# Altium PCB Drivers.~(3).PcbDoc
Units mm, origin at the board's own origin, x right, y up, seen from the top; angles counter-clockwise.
Board outline 55.43 x 48 mm, 2 copper layers (F.Cu, B.Cu); 24 components, 42 nets, 131 pads, 0 vias.
Unrouted connection lines stored in the file: 89.
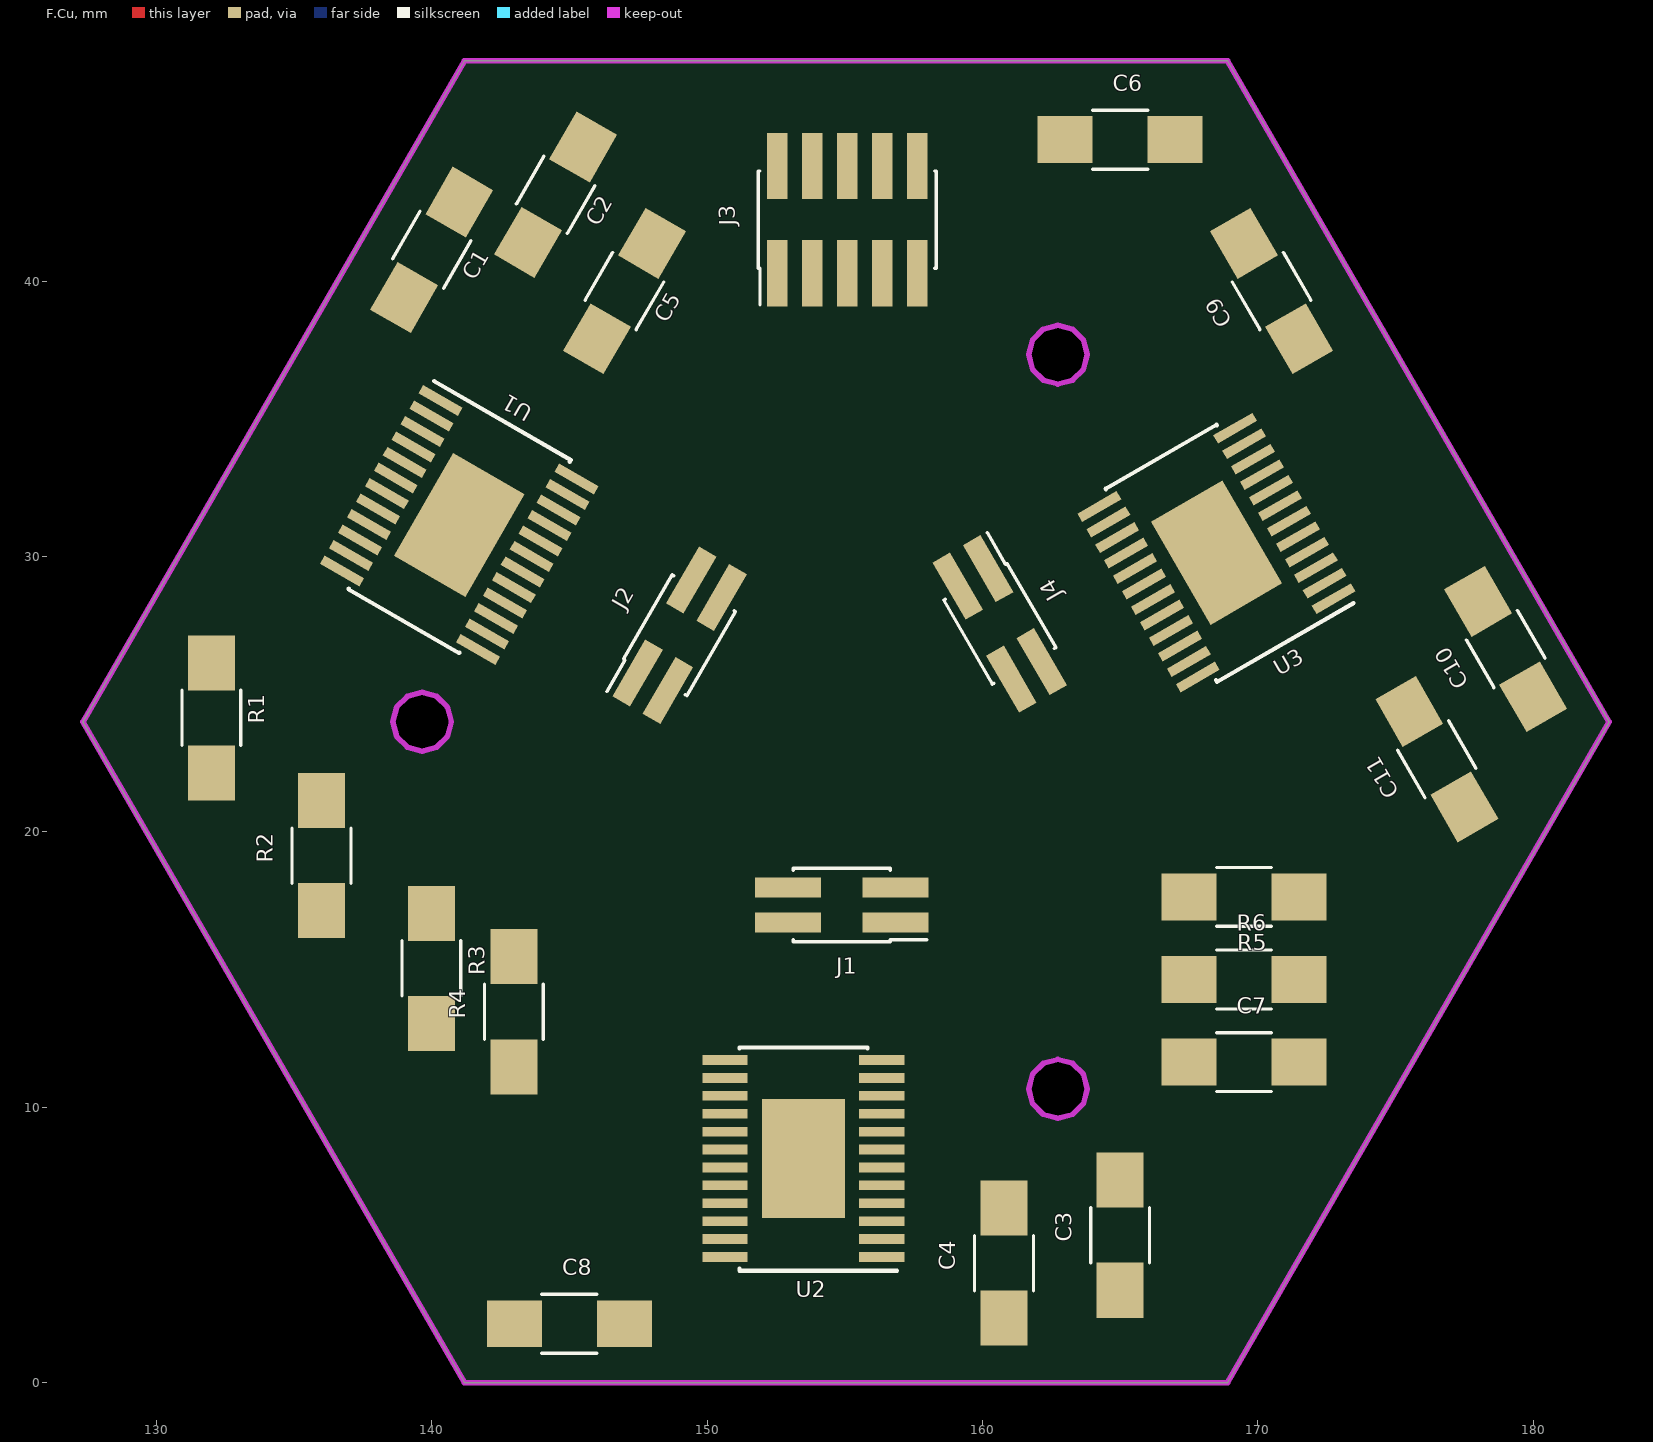
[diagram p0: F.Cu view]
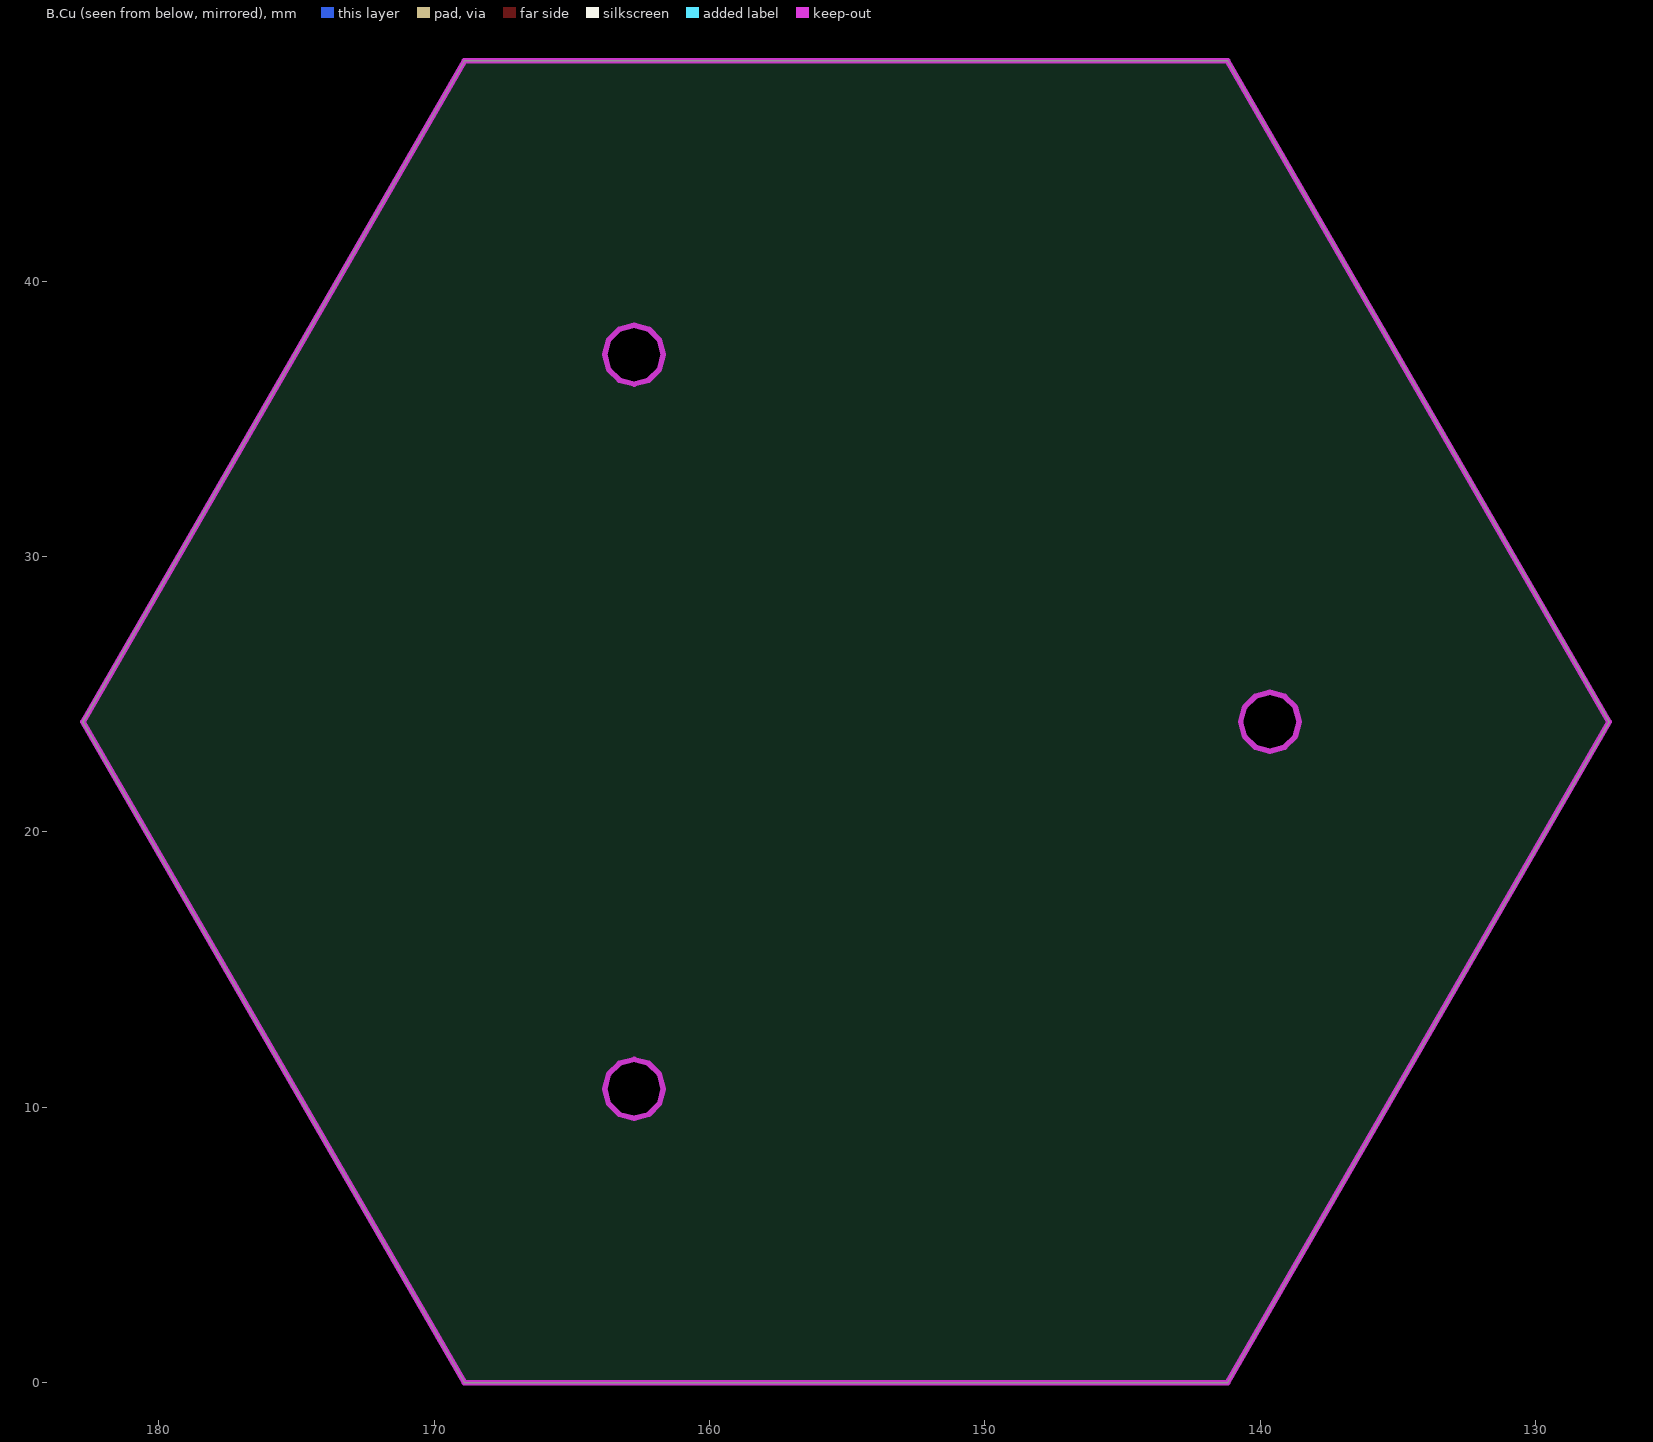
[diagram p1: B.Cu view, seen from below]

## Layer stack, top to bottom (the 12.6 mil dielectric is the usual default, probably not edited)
F.Mask: solder mask 0.0102, Solder Resist, Dk 3.5
F.Cu: signal copper 0.0356
Dielectric 1: dielectric 0.32, FR-4, Dk 4.8
B.Cu: signal copper 0.0356
B.Mask: solder mask 0.0102, Solder Resist, Dk 3.5

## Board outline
168.902,0 182.758,24 168.902,48 141.189,48 127.333,24 141.189,0 168.902,0
cut-out: 139.649,25.067 139.116,24.924 138.726,24.534 138.583,24 138.726,23.467 139.116,23.076 139.649,22.934 140.183,23.076 140.573,23.467 140.716,24 140.573,24.534 140.183,24.924 139.649,25.067
cut-out: 162.743,9.597 163.278,9.74 163.668,10.132 163.81,10.667 163.668,11.202 163.278,11.593 162.743,11.737 162.209,11.593 161.818,11.202 161.677,10.667 161.818,10.132 162.209,9.74 162.743,9.597
cut-out: 163.278,38.26 162.743,38.404 162.209,38.26 161.818,37.868 161.677,37.334 161.818,36.799 162.209,36.407 162.743,36.264 163.278,36.407 163.668,36.799 163.81,37.334 163.668,37.868 163.278,38.26

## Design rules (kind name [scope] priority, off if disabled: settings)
Clearance "Clearence 0.4_NetClass" [InNetClass('Back')] p1: gap=0.4 ignorepadtopadclearanceinfootprint=FALSE
Clearance "Clearence 0.28_NetClass" [InNetClass('Default')] p2: gap=0.28 ignorepadtopadclearanceinfootprint=FALSE
HoleSize "Hole Size (Default)" [All] p1: absolutevalues=TRUE maxlimit=10 minlimit=0.3 maxpercent=80.000 minpercent=20.000
MinimumSolderMaskSliver [All] p1: minsoldermaskwidth=0
PolygonConnect [All] p1: connectstyle=Direct reliefconductorwidth=0.254 reliefentries=4 polygonreliefangle="90 Angle" airgapwidth=0.254
RoutingVias [All] p1: holewidth=0.711 width=1.27 viastyle="Through Hole" minholewidth=0.711 minwidth=1.27 maxholewidth=0.711 maxwidth=1.27
SilkToSilkClearance [All] p1: silktosilkclearance=0
SilkToSolderMaskClearance [IsPad] p1: minsilkscreentomaskgap=0 clearancetoexposedcopper=TRUE
SolderMaskExpansion [All] p1: expansion=0.102 istentingtop=FALSE
Width [All] p1: maxlimit=0.254 minlimit=0.254 preferedwidth=0.254
26 further rules are at their usual default settings.

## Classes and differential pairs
net class Default: 1_1A 1_1B 1_2A 1_2B 1_DIR 1_STEP 2_1A 2_1B 2_2A 2_2B 2_DIR 2_STEP 3.3V 3_1A 3_1B 3_2A 3_2B 3_DIR 3_STEP 9V 12V GND MS1 Net-(C1-Pad1) Net-(C2-Pad1) Net-(C2-Pad2) Net-(C3-Pad1) Net-(C4-Pad1) Net-(C4-Pad2) Net-(C5-Pad2) Net-(C8-Pad2) Net-(C9-Pad1) Net-(C10-Pad1) Net-(C10-Pad2) Net-(C11-Pad2) Net-(R1-Pad1) Net-(R2-Pad2) Net-(R3-Pad1) Net-(R4-Pad2) Net-(R5-Pad1) Net-(R6-Pad2) RESET

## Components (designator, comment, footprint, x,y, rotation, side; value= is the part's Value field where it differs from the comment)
C1 "0.22uF" C_1206 140,41.14 r240 top
C2 "0.1uF" C_1206 144.5,43.14 r240 top
C3 "0.22uF" C_1206 165,5.357 r90 top
C4 "0.1uF" C_1206 160.782,4.341 r90 top
C5 "0.1uF" C_1206 147,39.64 r240 top
C6 "0.22uF" C_1206 165,45.14 r0 top
C7 "100uF" C_1206 169.5,11.64 r0 top
C8 "0.1uF" C_1206 145,2.14 r0 top
C9 "0.22uF" C_1206 170.5,39.64 r120 top
C10 "0.1uF" C_1206 179,26.64 r120 top
C11 "0.1uF" C_1206 176.5,22.64 r120 top
J1 "Conn_02x02" PinHeader_2x02_P1.27mm_Vertical_SMD 154.889,17.345 r180 top
J2 "Conn_02x02" PinHeader_2x02_P1.27mm_Vertical_SMD 149,27.14 r60 top
J3 "Conn_PinHeader_2x05_P1.27mm_Vertical_SMD" PinHeader_2x05_P1.27mm_Vertical_SMD 155.092,42.237 r90 top
J4 "Conn_02x02" PinHeader_2x02_P1.27mm_Vertical_SMD 160.63,27.556 r300 top
R1 "3.4" R_1206 132,24.14 r270 top
R2 "3.4" R_1206 136,19.14 r90 top
R3 "3.4" R_1206 139.989,15.043 r270 top
R4 "3.4" R_1206 142.986,13.469 r90 top
R5 "3.4" R_1206 169.5,17.64 r180 top
R6 "3.4" R_1206 169.5,14.64 r0 top
U1 "MotorDriver_BipolarStepper_A4982" 24-TSSOP-EP 141,31.14 r330 top
U2 "MotorDriver_BipolarStepper_A4982" 24-TSSOP-EP 153.5,8.14 r180 top
U3 "MotorDriver_BipolarStepper_A4982" 24-TSSOP-EP 168.5,30.14 r210 top

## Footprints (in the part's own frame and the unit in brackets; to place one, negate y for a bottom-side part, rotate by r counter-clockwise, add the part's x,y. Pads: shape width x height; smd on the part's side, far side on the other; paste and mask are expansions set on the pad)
24-TSSOP-EP [mm]
  rect 1.65x0.35 smd mask+0: 1(-2.85,3.575) 2(-2.85,2.925) 3(-2.85,2.275) 4(-2.85,1.625) 5(-2.85,0.975) 6(-2.85,0.325) 7(-2.85,-0.325) 8(-2.85,-0.975) 9(-2.85,-1.625) 10(-2.85,-2.275) 11(-2.85,-2.925) 12(-2.85,-3.575) 13(2.85,-3.575) 14(2.85,-2.925) 15(2.85,-2.275) 16(2.85,-1.625) 17(2.85,-0.975) 18(2.85,-0.325) 19(2.85,0.325) 20(2.85,0.975) 21(2.85,1.625) 22(2.85,2.275) 23(2.85,2.925) 24(2.85,3.575)
  rect 3x4.32 smd mask+0: 25(0,0)
  silkscreen extent -3.4,-4.03 2.32,4.08
C_1206 [mm]
  rect 2x1.7 smd mask+0: 1(-2,0) 2(2,0)
  silkscreen extent -1,-1.07 1,1.07
PinHeader_2x02_P1.27mm_Vertical_SMD [mm]
  rect 2.4x0.74 smd mask+0: 1(-1.95,0.635) 2(1.95,0.635) 3(-1.95,-0.635) 4(1.95,-0.635)
  silkscreen extent -3.09,-1.33 1.77,1.33
PinHeader_2x05_P1.27mm_Vertical_SMD [mm]
  rect 2.4x0.74 smd mask+0: 1(-1.95,2.54) 2(1.95,2.54) 3(-1.95,1.27) 4(1.95,1.27) 5(-1.95,0) 6(1.95,0) 7(-1.95,-1.27) 8(1.95,-1.27) 9(-1.95,-2.54) 10(1.95,-2.54)
  silkscreen extent -3.09,-3.23 1.77,3.23
R_1206 [mm]
  rect 2x1.7 smd mask+0: 1(-2,0) 2(2,0)
  silkscreen extent -1,-1.07 1,1.07

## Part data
C1 C2 C3 C4 C5 C6 C7 C8 C9 C10 C11: library part C_1206, "Capacitor SMD 1206, hand soldering"
J1 J2 J4: library part PinHeader_2x02_P1.27mm_Vertical_SMD, "surface-mounted straight pin header, 2x02, 1.27mm pitch, double rows"
J3: library part PinHeader_2x05_P1.27mm_Vertical_SMD, "surface-mounted straight pin header, 2x05, 1.27mm pitch, double rows"
R1 R2 R3 R4 R5 R6: library part R_1206, "Resistor SMD 1206, hand soldering"
U1 U2 U3: library part 24-TSSOP-EP, "TSSOP24: plastic thin shrink small outline package; 24 leads; body width 4.4 mm; (see NXP SSOP-TSSOP-VSO-REFLOW.pdf and sot355-1_po.pdf)"

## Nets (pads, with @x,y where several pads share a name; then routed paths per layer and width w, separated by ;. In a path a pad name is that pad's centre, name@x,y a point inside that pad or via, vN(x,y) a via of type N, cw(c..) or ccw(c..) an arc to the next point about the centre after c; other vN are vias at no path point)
1_1A: J1.1 U2.18
1_1B: J1.3 U2.15
1_2A: J1.4 U2.19
1_2B: J1.2 U2.22
1_DIR: J3.7 U2.14
1_STEP: J3.5 U2.11
2_1A: J4.1 U3.18
2_1B: J4.3 U3.15
2_2A: J4.4 U3.19
2_2B: J4.2 U3.22
2_DIR: J3.8 U3.14
2_STEP: J3.6 U3.11
3.3V: C6.2 J3.3 U1.9 U1.10 U1.12 U2.9 U2.10 U2.12 U3.9 U3.10 U3.12
3_1A: J2.1 U1.18
3_1B: J2.3 U1.15
3_2A: J2.4 U1.19
3_2B: J2.2 U1.22
3_DIR: J3.10 U1.14
3_STEP: J3.9 U1.11
9V: C8.1 J3.1 U2.16 U2.21
12V: C5.1 C7.2 C11.1 U1.16 U1.21 U3.16 U3.21
GND: C1.2 C3.2 C6.1 C7.1 C9.2 J3.2 R1.2 R2.1 R3.2 R4.1 R5.2 R6.1 U1.6 U1.8 U1.13 U1.23 U1.24 U1.25 U2.6 U2.8 U2.13 U2.23 U2.24 U2.25 U3.6 U3.8 U3.13 U3.23 U3.24 U3.25
MS1: J3.4 U1.5 U2.5 U3.5
Net-(C1-Pad1): C1.1 U1.4
Net-(C2-Pad1): C2.1 U1.1
Net-(C2-Pad2): C2.2 U1.2
Net-(C3-Pad1): C3.1 U2.4
Net-(C4-Pad1): C4.1 U2.1
Net-(C4-Pad2): C4.2 U2.2
Net-(C5-Pad2): C5.2 U1.3
Net-(C8-Pad2): C8.2 U2.3
Net-(C9-Pad1): C9.1 U3.4
Net-(C10-Pad1): C10.1 U3.1
Net-(C10-Pad2): C10.2 U3.2
Net-(C11-Pad2): C11.2 U3.3
Net-(R1-Pad1): R1.1 U1.20
Net-(R2-Pad2): R2.2 U1.17
Net-(R3-Pad1): R3.1 U2.20
Net-(R4-Pad2): R4.2 U2.17
Net-(R5-Pad1): R5.1 U3.20
Net-(R6-Pad2): R6.2 U3.17
RESET: U1.7 U2.7 U3.7

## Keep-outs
Edge.Cuts:
  lines w0.2: 127.333,24 141.189,0 ; 127.333,24 141.189,48 ; 127.333,24 141.189,0 ; 127.333,24 141.189,48 ; 140.716,24 140.716,24 ; 140.716,24 140.573,24.534 140.183,24.924 139.649,25.067 139.116,24.924 138.726,24.534 138.583,24 138.726,23.467 139.116,23.076 139.649,22.934 140.183,23.076 140.573,23.467 140.716,24 ; 141.189,0 168.902,0 ; 141.189,0 168.902,0 ; 141.189,48 168.902,48 ; 141.189,48 168.902,48 ; 168.902,0 182.758,24 ; 168.902,0 182.758,24 ; 168.902,48 182.758,24 ; 168.902,48 182.758,24 ; 161.677,10.667 161.818,10.132 162.209,9.74 162.743,9.597 163.278,9.74 163.668,10.132 163.81,10.667 163.668,11.202 163.278,11.593 162.743,11.737 162.209,11.593 161.818,11.202 161.677,10.667 ; 161.677,37.334 161.818,36.799 162.209,36.407 162.743,36.264 163.278,36.407 163.668,36.799 163.81,37.334 163.668,37.868 163.278,38.26 162.743,38.404 162.209,38.26 161.818,37.868 161.677,37.334

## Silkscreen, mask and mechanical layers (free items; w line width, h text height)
Dwgs.User:
  lines w0.2: 146.286,25.363 149.057,23.763 152.257,29.306 149.486,30.906 146.286,25.363 ; 149.712,41.066 160.379,41.066 160.379,44.267 149.712,44.267 149.712,41.066 ; 151.845,15.734 158.245,15.734 158.245,18.934 151.845,18.934 151.845,15.734 ; 157.833,29.306 161.033,23.763 163.804,25.363 160.604,30.906 157.833,29.306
